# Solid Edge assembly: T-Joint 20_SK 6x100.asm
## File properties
Author: fknapp
Template: iso metric assembly.asm
Last saved by: fknapp
Revision: 8
Application: Solid Edge
Username: fknapp
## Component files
Rundzylinderscheibe_8er_Schraube_45_V3.par
SK_Schraube_6x100.par
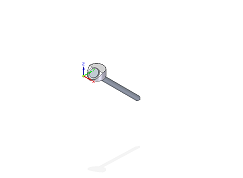
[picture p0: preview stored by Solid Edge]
